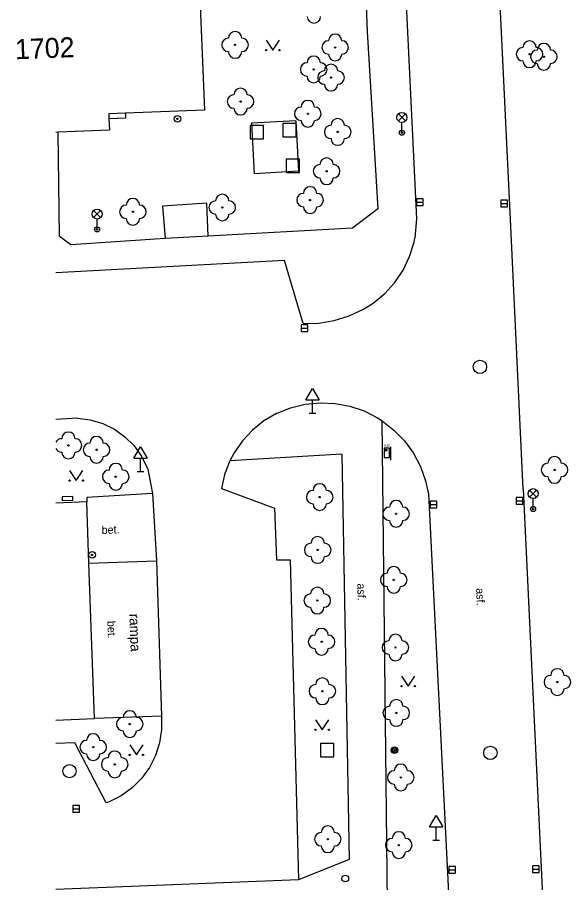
# Model space of a CAD drawing. Extents: x -640201 to -639641, y -1044739 to -1044317.
# Drawn here: x -640201.4 to -640160, y -1044553.9 to -1044489 of the extents above; entities that cross this region are included whole.
import ezdxf

# ---------------------------------------------------------------- set-up
doc = ezdxf.new("R2010")
doc.units = 0
for name, color, linetype in [('Budovy', 7, 'Continuous'), ('Popis objektů', 7, 'Continuous'), ('Popis povrchů', 7, 'Continuous'), ('Popis ČP_ ČE', 7, 'Continuous'), ('Pris-HUP', 7, 'Continuous'), ('Rozhraní ploch 1', 7, 'Continuous'), ('Rozhraní ploch 2', 7, 'Continuous'), ('Sloupy_označník', 7, 'Continuous'), ('Zeleň - stromy', 7, 'Continuous'), ('Znaky doprava', 7, 'Continuous'), ('Znaky kanalizace', 7, 'Continuous'), ('Znaky voda', 7, 'Continuous'), ('Značky doprava', 7, 'Continuous'), ('Značky KM', 7, 'Continuous'), ('Značky předmětů', 7, 'Continuous'), ('Šachty ner_', 7, 'Continuous')]:
    doc.layers.add(name, color=color, linetype=linetype)

msp = doc.modelspace()

# ---------------------------------------------------------------- linework, layer by layer
at = {"layer": 'Budovy'}
for p, q in [((-640187.87, -1044484.65), (-640187.4, -1044495.97)), ((-640193.344, -1044496.21), (-640194.58, -1044496.26)), ((-640194.58, -1044496.26), (-640194.569, -1044496.591)), ((-640187.4, -1044495.97), (-640193.344, -1044496.21)), ((-640194.569, -1044496.591), (-640194.54, -1044497.47)), ((-640198.384, -1044497.632), (-640198.551, -1044497.639)), ((-640194.54, -1044497.47), (-640198.384, -1044497.632)), ((-640196.24, -1044525.33), (-640198.551, -1044525.424)), ((-640196.073, -1044529.938), (-640196.24, -1044525.33)), ((-640195.65, -1044541.57), (-640196.073, -1044529.938)), ((-640198.551, -1044541.694), (-640195.65, -1044541.57))]:
    msp.add_line(p, q, dxfattribs=at)
at = {"layer": 'Pris-HUP'}
for p, q in [((-640193.344, -1044496.21), (-640193.33, -1044496.55)), ((-640194.569, -1044496.591), (-640193.33, -1044496.55)), ((-640197.28, -1044524.94), (-640198.09, -1044524.97)), ((-640198.09, -1044524.97), (-640198.079, -1044525.27)), ((-640197.269, -1044525.24), (-640197.28, -1044524.94)), ((-640197.269, -1044525.24), (-640198.079, -1044525.27))]:
    msp.add_line(p, q, dxfattribs=at)
at = {"layer": 'Rozhraní ploch 1'}
for p, q in [((-640175.58, -1044481.54), (-640175.21, -1044490.07)), ((-640164.48, -1044504.16), (-640165.52, -1044482.6)), ((-640172.49, -1044483.97), (-640171.53, -1044504.12)), ((-640175.21, -1044490.07), (-640174.42, -1044503.38)), ((-640198.29, -1044505.44), (-640198.384, -1044497.632)), ((-640187.23, -1044502.95), (-640190.56, -1044503.16)), ((-640190.56, -1044503.16), (-640190.37, -1044505.6)), ((-640187.13, -1044505.42), (-640187.23, -1044502.95)), ((-640174.42, -1044503.38), (-640176.32, -1044504.82)), ((-640171.53, -1044504.12), (-640171.64, -1044505.56)), ((-640163.54, -1044524.38), (-640164.48, -1044504.16)), ((-640176.32, -1044504.82), (-640187.13, -1044505.42)), ((-640197.42, -1044506.07), (-640198.29, -1044505.44)), ((-640190.37, -1044505.6), (-640197.42, -1044506.07)), ((-640181.41, -1044507.25), (-640198.551, -1044508.176)), ((-640180.03, -1044511.97), (-640181.41, -1044507.25)), ((-640196.93, -1044519.07), (-640198.551, -1044519.166)), ((-640173.68, -1044555.99), (-640174.11, -1044519.25)), ((-640177.11, -1044521.76), (-640185.51, -1044522.26)), ((-640177.11, -1044521.76), (-640176.57, -1044552.15)), ((-640191.66, -1044522.89), (-640191.32, -1044524.72)), ((-640186.15, -1044524.33), (-640182.17, -1044525.81)), ((-640191.32, -1044524.72), (-640196.24, -1044525)), ((-640191.32, -1044524.72), (-640191, -1044529.75)), ((-640170.63, -1044524.76), (-640169.09, -1044555.14)), ((-640163.54, -1044524.38), (-640162.05, -1044555.51)), ((-640196.24, -1044525), (-640196.24, -1044525.33)), ((-640182.17, -1044525.81), (-640182.01, -1044529.68)), ((-640182.01, -1044529.68), (-640180.98, -1044529.68)), ((-640180.98, -1044529.68), (-640180.38, -1044553.66)), ((-640197.14, -1044543.4), (-640198.551, -1044543.459)), ((-640194.77, -1044547.9), (-640197.14, -1044543.4)), ((-640176.57, -1044552.15), (-640180.38, -1044553.66)), ((-640180.38, -1044553.66), (-640198.551, -1044554.395))]:
    msp.add_line(p, q, dxfattribs=at)
for points in [[(-640174.76, -1044510.44), (-640173.9, -1044509.723), (-640173.151, -1044508.89), (-640172.528, -1044507.959), (-640172.044, -1044506.95), (-640171.709, -1044505.881), (-640171.64, -1044505.56)], [(-640180.03, -1044511.97), (-640178.851, -1044511.935), (-640177.687, -1044511.741), (-640176.56, -1044511.391), (-640175.491, -1044510.892), (-640174.76, -1044510.44)], [(-640182.01, -1044518.71), (-640180.966, -1044518.289), (-640179.873, -1044518.02), (-640178.753, -1044517.908), (-640177.629, -1044517.956), (-640176.522, -1044518.163), (-640175.456, -1044518.524), (-640174.452, -1044519.033), (-640174.11, -1044519.25)], [(-640196.93, -1044519.07), (-640195.968, -1044519.189), (-640195.039, -1044519.464), (-640194.168, -1044519.888), (-640193.379, -1044520.449), (-640192.692, -1044521.133), (-640192.127, -1044521.92), (-640191.699, -1044522.789), (-640191.66, -1044522.89)], [(-640182.01, -1044518.71), (-640182.96, -1044519.267), (-640183.819, -1044519.956), (-640184.57, -1044520.761), (-640185.196, -1044521.667), (-640185.51, -1044522.26)], [(-640174.11, -1044519.25), (-640173.214, -1044519.949), (-640172.425, -1044520.768), (-640171.759, -1044521.688), (-640171.228, -1044522.693), (-640170.844, -1044523.763), (-640170.63, -1044524.76)], [(-640185.51, -1044522.26), (-640185.91, -1044523.293), (-640186.15, -1044524.33)], [(-640190.64, -1044541.39), (-640190.631, -1044542.396), (-640190.781, -1044543.391), (-640191.087, -1044544.35), (-640191.541, -1044545.248), (-640192.131, -1044546.063), (-640192.842, -1044546.774), (-640193.658, -1044547.364), (-640194.556, -1044547.817), (-640194.77, -1044547.9)]]:
    msp.add_lwpolyline(points, dxfattribs=at)
at = {"layer": 'Rozhraní ploch 2'}
for p, q in [((-640180.566, -1044496.766), (-640183.886, -1044496.946)), ((-640183.886, -1044496.946), (-640183.68, -1044500.74)), ((-640180.566, -1044496.766), (-640180.36, -1044500.56)), ((-640180.36, -1044500.56), (-640183.68, -1044500.74)), ((-640187.13, -1044505.42), (-640190.37, -1044505.6)), ((-640196.073, -1044529.938), (-640191, -1044529.75)), ((-640191, -1044529.75), (-640190.64, -1044541.39)), ((-640190.64, -1044541.39), (-640195.65, -1044541.57))]:
    msp.add_line(p, q, dxfattribs=at)
at = {"layer": 'Sloupy_označník'}
for centre, radius in [((-640189.44, -1044496.62), 0.25), ((-640189.44, -1044496.62), 0.05), ((-640195.84, -1044529.31), 0.25), ((-640195.84, -1044529.31), 0.05), ((-640173.17, -1044543.94), 0.25), ((-640173.17, -1044543.94), 0.158), ((-640173.17, -1044543.94), 0.05)]:
    msp.add_circle(centre, radius, dxfattribs=at)
at = {"layer": 'Zeleň - stromy'}
for centre in [(-640185.12, -1044491.08), (-640177.62, -1044491.27), (-640163.05, -1044491.78), (-640161.98, -1044491.97), (-640179.23, -1044492.92), (-640177.93, -1044493.53), (-640184.71, -1044495.33), (-640179.67, -1044496.24), (-640177.43, -1044497.61), (-640178.26, -1044500.55), (-640179.5, -1044502.71), (-640192.78, -1044503.59), (-640186.08, -1044503.27), (-640197.61, -1044521.1), (-640195.5, -1044521.43), (-640161.18, -1044522.94), (-640194.06, -1044523.45), (-640178.78, -1044524.98), (-640173.05, -1044526.23), (-640178.93, -1044528.94), (-640173.23, -1044531.18), (-640178.96, -1044532.73), (-640178.64, -1044535.82), (-640173.1, -1044536.25), (-640160.97, -1044538.84), (-640178.58, -1044539.53), (-640173.04, -1044541.16), (-640193.01, -1044541.99), (-640195.75, -1044543.72), (-640194.14, -1044545.01), (-640172.7, -1044545.99), (-640178.17, -1044550.62), (-640172.85, -1044551.06)]:
    msp.add_circle(centre, 0.05, dxfattribs=at)
for centre, start, end in [((-640179.21, -1044488.95), 180, 0), ((-640185.62, -1044491.08), 90, 270), ((-640185.12, -1044490.58), 0, 180), ((-640184.62, -1044491.08), 270, 90), ((-640177.62, -1044490.77), 0, 180), ((-640178.12, -1044491.27), 90, 270), ((-640177.12, -1044491.27), 270, 90), ((-640163.05, -1044491.28), 0, 180), ((-640161.98, -1044491.47), 0, 180), ((-640185.12, -1044491.58), 180, 0), ((-640177.62, -1044491.77), 180, 0), ((-640163.55, -1044491.78), 90, 270), ((-640162.48, -1044491.97), 90, 270), ((-640162.55, -1044491.78), 270, 90), ((-640161.48, -1044491.97), 270, 90), ((-640179.73, -1044492.92), 90, 270), ((-640179.23, -1044492.42), 0, 180), ((-640178.73, -1044492.92), 270, 90), ((-640177.93, -1044493.03), 0, 180), ((-640163.05, -1044492.28), 180, 0), ((-640161.98, -1044492.47), 180, 0), ((-640178.43, -1044493.53), 90, 270), ((-640177.43, -1044493.53), 270, 90), ((-640179.23, -1044493.42), 180, 0), ((-640184.71, -1044494.83), 0, 180), ((-640177.93, -1044494.03), 180, 0), ((-640185.21, -1044495.33), 90, 270), ((-640184.21, -1044495.33), 270, 90), ((-640180.17, -1044496.24), 90, 270), ((-640179.67, -1044495.74), 0, 180), ((-640179.17, -1044496.24), 270, 90), ((-640184.71, -1044495.83), 180, 0), ((-640179.67, -1044496.74), 180, 0), ((-640177.43, -1044497.11), 0, 180), ((-640177.93, -1044497.61), 90, 270), ((-640176.93, -1044497.61), 270, 90), ((-640177.43, -1044498.11), 180, 0), ((-640178.26, -1044500.05), 0, 180), ((-640178.76, -1044500.55), 90, 270), ((-640177.76, -1044500.55), 270, 90), ((-640178.26, -1044501.05), 180, 0), ((-640186.08, -1044502.77), 0, 180), ((-640180, -1044502.71), 90, 270), ((-640179.5, -1044502.21), 0, 180), ((-640179, -1044502.71), 270, 90), ((-640192.78, -1044503.09), 0, 180), ((-640186.58, -1044503.27), 90, 270), ((-640185.58, -1044503.27), 270, 90), ((-640193.28, -1044503.59), 90, 270), ((-640192.28, -1044503.59), 270, 90), ((-640179.5, -1044503.21), 180, 0), ((-640192.78, -1044504.09), 180, 0), ((-640186.08, -1044503.77), 180, 0), ((-640197.61, -1044520.6), 0, 180), ((-640195.5, -1044520.93), 0, 180), ((-640198.11, -1044521.1), 90, 151.92186), ((-640197.11, -1044521.1), 270, 90), ((-640196, -1044521.43), 90, 270), ((-640195, -1044521.43), 270, 90), ((-640198.11, -1044521.1), 208.07814, 270), ((-640197.61, -1044521.6), 180, 0), ((-640195.5, -1044521.93), 180, 0), ((-640161.18, -1044522.44), 0, 180), ((-640194.56, -1044523.45), 90, 270), ((-640194.06, -1044522.95), 0, 180), ((-640193.56, -1044523.45), 270, 90), ((-640161.68, -1044522.94), 90, 270), ((-640160.68, -1044522.94), 270, 90), ((-640161.18, -1044523.44), 180, 0), ((-640194.06, -1044523.95), 180, 0), ((-640178.78, -1044524.48), 0, 180), ((-640179.28, -1044524.98), 90, 270), ((-640178.28, -1044524.98), 270, 90), ((-640178.78, -1044525.48), 180, 0), ((-640173.05, -1044525.73), 0, 180), ((-640173.55, -1044526.23), 90, 270), ((-640172.55, -1044526.23), 270, 90), ((-640173.05, -1044526.73), 180, 0), ((-640178.93, -1044528.44), 0, 180), ((-640179.43, -1044528.94), 90, 270), ((-640178.43, -1044528.94), 270, 90), ((-640178.93, -1044529.44), 180, 0), ((-640173.73, -1044531.18), 90, 270), ((-640173.23, -1044530.68), 0, 180), ((-640172.73, -1044531.18), 270, 90), ((-640178.96, -1044532.23), 0, 180), ((-640173.23, -1044531.68), 180, 0), ((-640179.46, -1044532.73), 90, 270), ((-640178.46, -1044532.73), 270, 90), ((-640178.96, -1044533.23), 180, 0), ((-640179.14, -1044535.82), 90, 270), ((-640178.64, -1044535.32), 0, 180), ((-640178.14, -1044535.82), 270, 90), ((-640173.1, -1044535.75), 0, 180), ((-640173.6, -1044536.25), 90, 270), ((-640172.6, -1044536.25), 270, 90), ((-640178.64, -1044536.32), 180, 0), ((-640173.1, -1044536.75), 180, 0), ((-640160.97, -1044538.34), 0, 180), ((-640178.58, -1044539.03), 0, 180), ((-640161.47, -1044538.84), 90, 270), ((-640160.47, -1044538.84), 270, 90), ((-640179.08, -1044539.53), 90, 270), ((-640178.08, -1044539.53), 270, 90), ((-640160.97, -1044539.34), 180, 0), ((-640178.58, -1044540.03), 180, 0), ((-640173.04, -1044540.66), 0, 180), ((-640193.01, -1044541.49), 0, 180), ((-640173.54, -1044541.16), 90, 270), ((-640172.54, -1044541.16), 270, 90), ((-640193.51, -1044541.99), 90, 270), ((-640192.51, -1044541.99), 270, 90), ((-640173.04, -1044541.66), 180, 0), ((-640193.01, -1044542.49), 180, 0), ((-640195.75, -1044543.22), 0, 180), ((-640196.25, -1044543.72), 90, 270), ((-640195.25, -1044543.72), 270, 90), ((-640195.75, -1044544.22), 180, 0), ((-640194.14, -1044544.51), 0, 180), ((-640194.64, -1044545.01), 90, 270), ((-640193.64, -1044545.01), 270, 90), ((-640172.7, -1044545.49), 0, 180), ((-640194.14, -1044545.51), 180, 0), ((-640173.2, -1044545.99), 90, 270), ((-640172.2, -1044545.99), 270, 90), ((-640172.7, -1044546.49), 180, 0), ((-640178.17, -1044550.12), 0, 180), ((-640178.67, -1044550.62), 90, 270), ((-640177.67, -1044550.62), 270, 90), ((-640172.85, -1044550.56), 0, 180), ((-640173.35, -1044551.06), 90, 270), ((-640172.35, -1044551.06), 270, 90), ((-640178.17, -1044551.12), 180, 0), ((-640172.85, -1044551.56), 180, 0)]:
    msp.add_arc(centre, 0.5, start, end, dxfattribs=at)
at = {"layer": 'Znaky doprava'}
for p, q in [((-640172.885, -1044496.255), (-640172.355, -1044496.785)), ((-640172.885, -1044496.785), (-640172.355, -1044496.255)), ((-640172.62, -1044497.67), (-640172.62, -1044496.895)), ((-640195.725, -1044503.495), (-640195.195, -1044504.025)), ((-640195.725, -1044504.025), (-640195.195, -1044503.495)), ((-640195.46, -1044504.91), (-640195.46, -1044504.135)), ((-640163.055, -1044524.455), (-640162.525, -1044524.985)), ((-640163.055, -1044524.985), (-640162.525, -1044524.455)), ((-640162.79, -1044525.87), (-640162.79, -1044525.095))]:
    msp.add_line(p, q, dxfattribs=at)
for centre, radius in [((-640172.62, -1044496.52), 0.375), ((-640172.62, -1044497.67), 0.19), ((-640172.62, -1044497.67), 0.05), ((-640195.46, -1044503.76), 0.375), ((-640195.46, -1044504.91), 0.19), ((-640195.46, -1044504.91), 0.05), ((-640162.79, -1044524.72), 0.375), ((-640162.79, -1044525.87), 0.19), ((-640162.79, -1044525.87), 0.05)]:
    msp.add_circle(centre, radius, dxfattribs=at)
at = {"layer": 'Znaky kanalizace'}
for p, q in [((-640171.53, -1044502.88), (-640171.03, -1044502.88)), ((-640165.2, -1044502.98), (-640164.7, -1044502.98)), ((-640180.17, -1044512.31), (-640179.67, -1044512.31)), ((-640170.5, -1044525.54), (-640170, -1044525.54)), ((-640164.05, -1044525.26), (-640163.55, -1044525.26)), ((-640197.27, -1044548.34), (-640196.77, -1044548.34)), ((-640162.84, -1044552.87), (-640162.34, -1044552.87)), ((-640169.1, -1044552.92), (-640168.6, -1044552.92))]:
    msp.add_line(p, q, dxfattribs=at)
for points in [[(-640171.53, -1044503.13), (-640171.03, -1044503.13), (-640171.03, -1044502.63), (-640171.53, -1044502.63)], [(-640165.2, -1044503.23), (-640164.7, -1044503.23), (-640164.7, -1044502.73), (-640165.2, -1044502.73)], [(-640180.17, -1044512.56), (-640179.67, -1044512.56), (-640179.67, -1044512.06), (-640180.17, -1044512.06)], [(-640170.5, -1044525.79), (-640170, -1044525.79), (-640170, -1044525.29), (-640170.5, -1044525.29)], [(-640164.05, -1044525.51), (-640163.55, -1044525.51), (-640163.55, -1044525.01), (-640164.05, -1044525.01)], [(-640197.27, -1044548.59), (-640196.77, -1044548.59), (-640196.77, -1044548.09), (-640197.27, -1044548.09)], [(-640169.1, -1044553.17), (-640168.6, -1044553.17), (-640168.6, -1044552.67), (-640169.1, -1044552.67)], [(-640162.84, -1044553.12), (-640162.34, -1044553.12), (-640162.34, -1044552.62), (-640162.84, -1044552.62)]]:
    msp.add_lwpolyline(points, close=True, dxfattribs=at)
for centre in [(-640166.77, -1044515.22), (-640165.99, -1044544.15), (-640197.53, -1044545.52)]:
    msp.add_circle(centre, 0.5, dxfattribs=at)
at = {"layer": 'Znaky voda'}
msp.add_circle((-640176.86, -1044553.57), 0.25, dxfattribs=at)
at = {"layer": 'Značky doprava'}
for p, q in [((-640179.82, -1044517.69), (-640179.32, -1044516.84)), ((-640179.32, -1044516.84), (-640178.82, -1044517.69)), ((-640179.82, -1044517.69), (-640178.82, -1044517.69)), ((-640179.32, -1044518.69), (-640179.32, -1044517.69)), ((-640179.57, -1044518.69), (-640179.07, -1044518.69)), ((-640192.71, -1044522.05), (-640192.21, -1044521.2)), ((-640192.21, -1044521.2), (-640191.71, -1044522.05)), ((-640192.71, -1044522.05), (-640191.71, -1044522.05)), ((-640192.21, -1044523.05), (-640192.21, -1044522.05)), ((-640192.46, -1044523.05), (-640191.96, -1044523.05)), ((-640170.55, -1044549.69), (-640170.05, -1044548.84)), ((-640170.05, -1044548.84), (-640169.55, -1044549.69)), ((-640170.55, -1044549.69), (-640169.55, -1044549.69)), ((-640170.05, -1044550.69), (-640170.05, -1044549.69)), ((-640170.3, -1044550.69), (-640169.8, -1044550.69))]:
    msp.add_line(p, q, dxfattribs=at)
at = {"layer": 'Značky KM'}
for p, q in [((-640182.79, -1044490.722), (-640182.29, -1044491.472)), ((-640182.29, -1044491.472), (-640181.79, -1044490.722)), ((-640197.523, -1044522.991), (-640197.023, -1044523.741)), ((-640197.023, -1044523.741), (-640196.523, -1044522.991)), ((-640172.651, -1044538.388), (-640172.151, -1044539.138)), ((-640172.151, -1044539.138), (-640171.651, -1044538.388)), ((-640179.093, -1044541.67), (-640178.593, -1044542.42)), ((-640178.593, -1044542.42), (-640178.093, -1044541.67)), ((-640193.013, -1044543.558), (-640192.513, -1044544.308)), ((-640192.513, -1044544.308), (-640192.013, -1044543.558))]:
    msp.add_line(p, q, dxfattribs=at)
for centre in [(-640182.79, -1044491.472), (-640181.79, -1044491.472), (-640197.523, -1044523.741), (-640196.523, -1044523.741), (-640172.651, -1044539.138), (-640171.651, -1044539.138), (-640179.093, -1044542.42), (-640178.093, -1044542.42), (-640193.013, -1044544.308), (-640192.013, -1044544.308)]:
    msp.add_circle(centre, 0.05, dxfattribs=at)
at = {"layer": 'Značky předmětů'}
for p, q in [((-640173.54, -1044521.4), (-640173.44, -1044521.4)), ((-640173.44, -1044522.2), (-640173.44, -1044521.2)), ((-640173.54, -1044521.9), (-640173.44, -1044521.9))]:
    msp.add_line(p, q, dxfattribs=at)
msp.add_lwpolyline([(-640173.54, -1044521.3), (-640173.94, -1044521.3), (-640173.94, -1044521.4), (-640173.74, -1044521.4), (-640173.74, -1044521.5), (-640173.94, -1044521.5), (-640173.94, -1044522), (-640173.54, -1044522)], close=True, dxfattribs=at)
at = {"layer": 'Šachty ner_'}
for points in [[(-640181.54, -1044497.97), (-640180.54, -1044497.97), (-640180.54, -1044496.97), (-640181.54, -1044496.97)], [(-640183.99, -1044498.12), (-640182.99, -1044498.12), (-640182.99, -1044497.12), (-640183.99, -1044497.12)], [(-640181.3, -1044500.65), (-640180.3, -1044500.65), (-640180.3, -1044499.65), (-640181.3, -1044499.65)], [(-640178.73, -1044544.45), (-640177.73, -1044544.45), (-640177.73, -1044543.45), (-640178.73, -1044543.45)]]:
    msp.add_lwpolyline(points, close=True, dxfattribs=at)

# ---------------------------------------------------------------- texts
at = {"layer": 'Popis objektů'}
msp.add_text('rampa', height=0.75, rotation=272.11979, dxfattribs=at).set_placement((-640193.046, -1044533.729))
at = {"layer": 'Popis povrchů'}
for s, rotation, p in [('bet.', 2.11901, (-640195.109, -1044527.749)), ('asf.', 271.01798, (-640175.958, -1044531.45)), ('asf.', 272.90191, (-640167.066, -1044531.819)), ('bet.', 272.11979, (-640194.696, -1044534.263))]:
    msp.add_text(s, height=0.6, rotation=rotation, dxfattribs=at).set_placement(p)
at = {"layer": 'Popis ČP_ ČE'}
msp.add_text('1702', height=1.5, rotation=2.13691, dxfattribs=at).set_placement((-640201.586, -1044492.163))
at = {"layer": 'Značky předmětů'}
msp.add_text('koš', height=0.2, dxfattribs=at).set_placement((-640173.94, -1044521.2))

doc.saveas('drawing.dxf')
